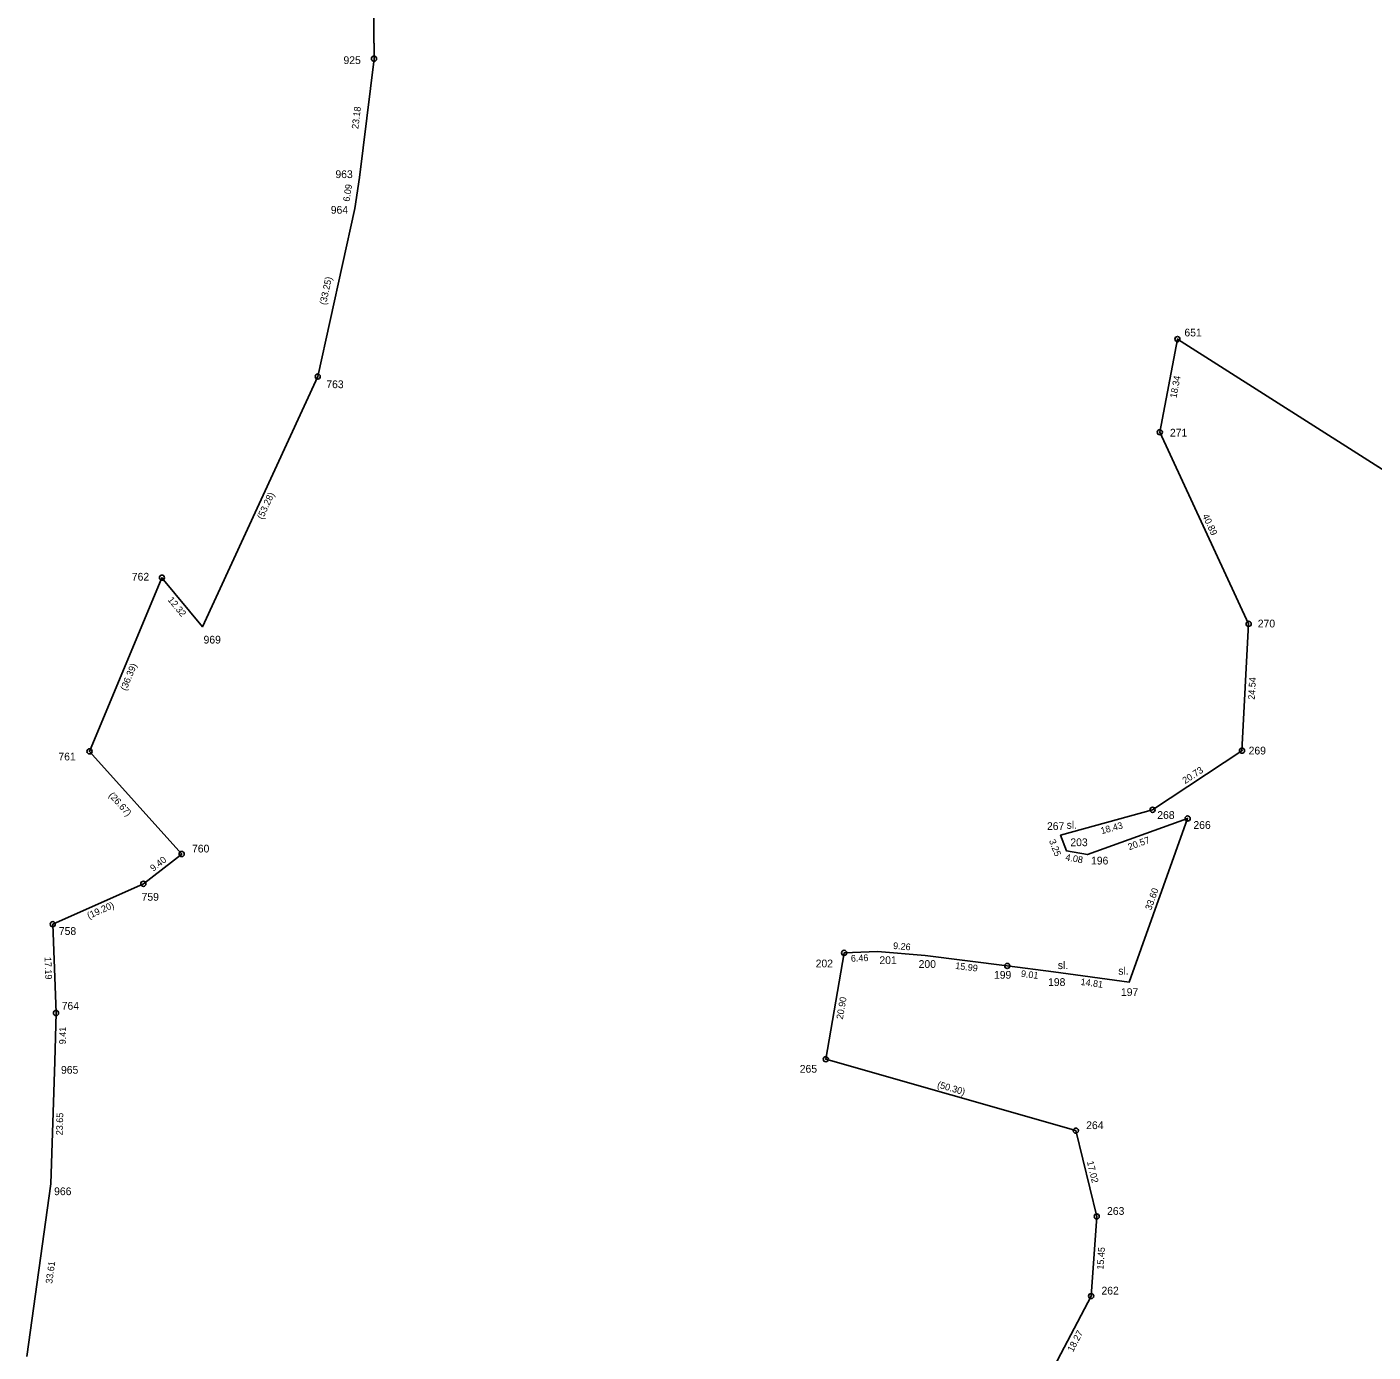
# Model space of a CAD drawing. Extents: x -555170 to -550532, y -1039598 to -1034701.
# Drawn here: x -552446.4 to -552186.1, y -1035785.1 to -1035528.8 of the extents above; entities that cross this region are included whole.
import ezdxf

# ---------------------------------------------------------------- set-up
doc = ezdxf.new("R2010")
doc.units = 0
for name, color, linetype in [('Vrstva 10', 7, 'Continuous'), ('Vrstva 40', 7, 'Continuous'), ('Vrstva 43', 7, 'Continuous'), ('Vrstva 48', 7, 'Continuous')]:
    doc.layers.add(name, color=color, linetype=linetype)

msp = doc.modelspace()

# ---------------------------------------------------------------- linework, layer by layer
at = {"layer": 'Vrstva 40'}
for p, q in [((-552379.43, -1035516.61), (-552379.29, -1035534.96)), ((-552379.29, -1035534.96), (-552382.08, -1035557.94)), ((-552382.08, -1035557.94), (-552383.01, -1035563.95)), ((-552383.01, -1035563.95), (-552390.18, -1035596.42)), ((-552227.34, -1035607.2), (-552223.93, -1035589.18)), ((-552223.93, -1035589.18), (-552103.96, -1035665.42)), ((-552390.18, -1035596.42), (-552412.47, -1035644.81)), ((-552210.15, -1035644.24), (-552227.34, -1035607.2)), ((-552420.31, -1035635.32), (-552434.31, -1035668.9)), ((-552412.47, -1035644.81), (-552420.31, -1035635.32)), ((-552211.44, -1035668.77), (-552210.15, -1035644.24)), ((-552434.31, -1035668.9), (-552416.49, -1035688.75)), ((-552228.74, -1035680.19), (-552211.44, -1035668.77)), ((-552246.53, -1035685.13), (-552228.74, -1035680.19)), ((-552221.95, -1035681.89), (-552241.34, -1035688.87)), ((-552233.24, -1035713.5), (-552221.95, -1035681.89)), ((-552245.36, -1035688.15), (-552246.53, -1035685.13)), ((-552241.34, -1035688.87), (-552245.36, -1035688.15)), ((-552416.49, -1035688.75), (-552423.9, -1035694.5)), ((-552423.9, -1035694.5), (-552441.43, -1035702.32)), ((-552441.43, -1035702.32), (-552440.79, -1035719.48)), ((-552291.93, -1035728.43), (-552288.38, -1035707.87)), ((-552288.38, -1035707.87), (-552281.91, -1035707.61)), ((-552281.91, -1035707.61), (-552272.68, -1035708.38)), ((-552272.68, -1035708.38), (-552256.83, -1035710.39)), ((-552256.83, -1035710.39), (-552247.92, -1035711.55)), ((-552247.92, -1035711.55), (-552233.24, -1035713.5)), ((-552440.79, -1035719.48), (-552441.01, -1035728.89)), ((-552441.01, -1035728.89), (-552441.77, -1035752.52)), ((-552243.57, -1035742.24), (-552291.93, -1035728.43)), ((-552239.53, -1035758.82), (-552243.57, -1035742.24)), ((-552441.77, -1035752.52), (-552446.42, -1035785.88)), ((-552240.61, -1035774.22), (-552239.53, -1035758.82)), ((-552249.09, -1035790.4), (-552240.61, -1035774.22))]:
    msp.add_line(p, q, dxfattribs=at)
at = {"layer": 'Vrstva 43'}
for p, q in [((-552379.29, -1035534.96), (-552379.29, -1035534.96)), ((-552382.08, -1035557.94), (-552382.08, -1035557.94)), ((-552383.01, -1035563.95), (-552383.01, -1035563.95)), ((-552223.93, -1035589.18), (-552223.93, -1035589.18)), ((-552390.18, -1035596.42), (-552390.18, -1035596.42)), ((-552227.34, -1035607.2), (-552227.34, -1035607.2)), ((-552420.31, -1035635.32), (-552420.31, -1035635.32)), ((-552210.15, -1035644.24), (-552210.15, -1035644.24)), ((-552412.47, -1035644.81), (-552412.47, -1035644.81)), ((-552434.31, -1035668.9), (-552434.31, -1035668.9)), ((-552211.44, -1035668.77), (-552211.44, -1035668.77)), ((-552228.74, -1035680.19), (-552228.74, -1035680.19)), ((-552221.95, -1035681.89), (-552221.95, -1035681.89)), ((-552246.53, -1035685.13), (-552246.53, -1035685.13)), ((-552245.36, -1035688.15), (-552245.36, -1035688.15)), ((-552416.49, -1035688.75), (-552416.49, -1035688.75)), ((-552241.34, -1035688.87), (-552241.34, -1035688.87)), ((-552423.9, -1035694.5), (-552423.9, -1035694.5)), ((-552441.43, -1035702.32), (-552441.43, -1035702.32)), ((-552288.38, -1035707.87), (-552288.38, -1035707.87)), ((-552281.91, -1035707.61), (-552281.91, -1035707.61)), ((-552272.68, -1035708.38), (-552272.68, -1035708.38)), ((-552256.83, -1035710.39), (-552256.83, -1035710.39)), ((-552247.92, -1035711.55), (-552247.92, -1035711.55)), ((-552233.24, -1035713.5), (-552233.24, -1035713.5)), ((-552440.79, -1035719.48), (-552440.79, -1035719.48)), ((-552441.01, -1035728.89), (-552441.01, -1035728.89)), ((-552291.93, -1035728.43), (-552291.93, -1035728.43)), ((-552243.57, -1035742.24), (-552243.57, -1035742.24)), ((-552441.77, -1035752.52), (-552441.77, -1035752.52)), ((-552239.53, -1035758.82), (-552239.53, -1035758.82)), ((-552240.61, -1035774.22), (-552240.61, -1035774.22))]:
    msp.add_line(p, q, dxfattribs=at)
for centre, radius in [((-552379.29, -1035534.96), 0.5), ((-552379.29, -1035534.96), 0.01), ((-552223.93, -1035589.18), 0.5), ((-552223.93, -1035589.18), 0.01), ((-552390.18, -1035596.42), 0.5), ((-552390.18, -1035596.42), 0.01), ((-552227.34, -1035607.2), 0.5), ((-552227.34, -1035607.2), 0.01), ((-552420.31, -1035635.32), 0.5), ((-552420.31, -1035635.32), 0.01), ((-552210.15, -1035644.24), 0.5), ((-552210.15, -1035644.24), 0.01), ((-552434.31, -1035668.9), 0.5), ((-552434.31, -1035668.9), 0.01), ((-552211.44, -1035668.77), 0.5), ((-552211.44, -1035668.77), 0.01), ((-552228.74, -1035680.19), 0.5), ((-552228.74, -1035680.19), 0.01), ((-552221.95, -1035681.89), 0.5), ((-552221.95, -1035681.89), 0.01), ((-552416.49, -1035688.75), 0.5), ((-552416.49, -1035688.75), 0.01), ((-552423.9, -1035694.5), 0.5), ((-552423.9, -1035694.5), 0.01), ((-552441.43, -1035702.32), 0.5), ((-552441.43, -1035702.32), 0.01), ((-552288.38, -1035707.87), 0.5), ((-552288.38, -1035707.87), 0.01), ((-552256.83, -1035710.39), 0.5), ((-552256.83, -1035710.39), 0.01), ((-552440.79, -1035719.49), 0.5), ((-552440.79, -1035719.49), 0.01), ((-552291.93, -1035728.43), 0.5), ((-552291.93, -1035728.43), 0.01), ((-552243.57, -1035742.24), 0.5), ((-552243.57, -1035742.24), 0.01), ((-552239.53, -1035758.82), 0.5), ((-552239.53, -1035758.82), 0.01), ((-552240.61, -1035774.22), 0.5), ((-552240.61, -1035774.22), 0.01)]:
    msp.add_circle(centre, radius, dxfattribs=at)
at = {"layer": 'Vrstva 48'}
for points in [[(-552446.42, -1035785.88), (-552441.77, -1035752.52), (-552441.01, -1035728.89), (-552440.79, -1035719.48), (-552441.43, -1035702.32), (-552423.9, -1035694.5), (-552416.49, -1035688.75), (-552434.31, -1035668.9), (-552420.31, -1035635.32), (-552412.47, -1035644.81), (-552390.18, -1035596.42), (-552383.01, -1035563.95), (-552382.08, -1035557.94), (-552379.29, -1035534.96), (-552379.43, -1035516.61)], [(-552103.96, -1035665.42), (-552223.93, -1035589.18), (-552227.34, -1035607.2), (-552210.15, -1035644.24), (-552211.44, -1035668.77), (-552228.74, -1035680.19), (-552246.53, -1035685.13), (-552245.36, -1035688.15), (-552241.34, -1035688.87), (-552221.95, -1035681.89), (-552233.24, -1035713.5), (-552247.92, -1035711.55), (-552256.83, -1035710.39), (-552272.68, -1035708.38), (-552281.91, -1035707.61), (-552288.38, -1035707.87), (-552291.93, -1035728.43), (-552243.57, -1035742.24), (-552239.53, -1035758.82), (-552240.61, -1035774.22), (-552249.09, -1035790.4)]]:
    msp.add_lwpolyline(points, dxfattribs=at)

# ---------------------------------------------------------------- texts
at = {"layer": 'Vrstva 10'}
for s, rotation, p in [('23.18', 83.0793, (-552382.34, -1035548.62)), ('6.09', 81.2037, (-552384.03, -1035562.68)), ('(33.25)', 77.5403, (-552388.59, -1035582.66)), ('18.34', 79.2673, (-552224.12, -1035600.67)), ('(53.28)', 65.2725, (-552400.81, -1035624.16)), ('40.89', 294.9021, (-552219.14, -1035623.34)), ('12.32', 309.5594, (-552419.27, -1035639.65)), ('(36.39)', 67.3813, (-552427.22, -1035657.28)), ('24.54', 86.9764, (-552208.97, -1035658.94)), ('20.73', 33.4295, (-552222.43, -1035675.24)), ('(26.67)', 311.9178, (-552430.7, -1035677.47)), ('18.43', 15.5238, (-552238.57, -1035684.93)), ('3.25', 291.1772, (-552248.79, -1035686.19)), ('20.57', 19.785, (-552233.23, -1035688.03)), ('9.40', 37.7775, (-552421.98, -1035692.19)), ('4.08', 349.8457, (-552245.66, -1035689.96)), ('33.60', 70.3389, (-552229, -1035699.7)), ('(19.20)', 24.0417, (-552434.44, -1035701.33)), ('9.26', 355.2312, (-552278.95, -1035707.1)), ('17.19', 272.1459, (-552443.01, -1035708.68)), ('6.46', 2.3012, (-552287.05, -1035709.58)), ('15.99', 352.7727, (-552266.94, -1035710.95)), ('9.01', 352.5823, (-552254.25, -1035712.48)), ('14.81', 352.4335, (-552242.71, -1035714.06)), ('20.90', 80.1971, (-552288.63, -1035720.79)), ('9.41', 88.6363, (-552438.91, -1035725.55)), ('(50.30)', 344.0584, (-552270.48, -1035733.88)), ('23.65', 88.1579, (-552439.52, -1035743.14)), ('17.02', 283.6952, (-552241.44, -1035748.25)), ('15.45', 85.973, (-552238.24, -1035769.14)), ('33.61', 82.0638, (-552441.54, -1035771.89)), ('18.27', 62.3638, (-552244.13, -1035785.15))]:
    msp.add_text(s, height=1.3, rotation=rotation, dxfattribs=at).set_placement(p)
at = {"layer": 'Vrstva 43'}
for s, p in [('925', (-552385.2, -1035536)), ('963', (-552386.76, -1035558.05)), ('964', (-552387.66, -1035564.94)), ('651', (-552222.57, -1035588.67)), ('763', (-552388.52, -1035598.67)), ('271', (-552225.37, -1035608.03)), ('762', (-552426.13, -1035635.88)), ('270', (-552208.38, -1035644.94)), ('969', (-552412.26, -1035648.05)), ('761', (-552440.33, -1035670.65)), ('269', (-552210.15, -1035669.5)), ('268', (-552227.82, -1035681.96)), ('267', (-552249.15, -1035684.1)), ('sl.', (-552245.34, -1035683.87)), ('266', (-552220.83, -1035683.89)), ('203', (-552244.63, -1035687.23)), ('760', (-552414.49, -1035688.45)), ('196', (-552240.63, -1035690.77)), ('759', (-552424.24, -1035697.78)), ('758', (-552440.24, -1035704.39)), ('202', (-552293.88, -1035710.66)), ('201', (-552281.56, -1035710.03)), ('200', (-552273.97, -1035710.77)), ('sl.', (-552247.06, -1035711)), ('199', (-552259.4, -1035712.86)), ('sl.', (-552235.36, -1035712.08)), ('198', (-552248.94, -1035714.26)), ('197', (-552234.85, -1035716.2)), ('764', (-552439.69, -1035718.85)), ('965', (-552439.83, -1035731.23)), ('265', (-552296.96, -1035731.03)), ('264', (-552241.57, -1035741.94)), ('966', (-552441.16, -1035754.71)), ('263', (-552237.53, -1035758.52)), ('262', (-552238.61, -1035773.92))]:
    msp.add_text(s, height=1.5, dxfattribs=at).set_placement(p)

doc.saveas('drawing.dxf')
